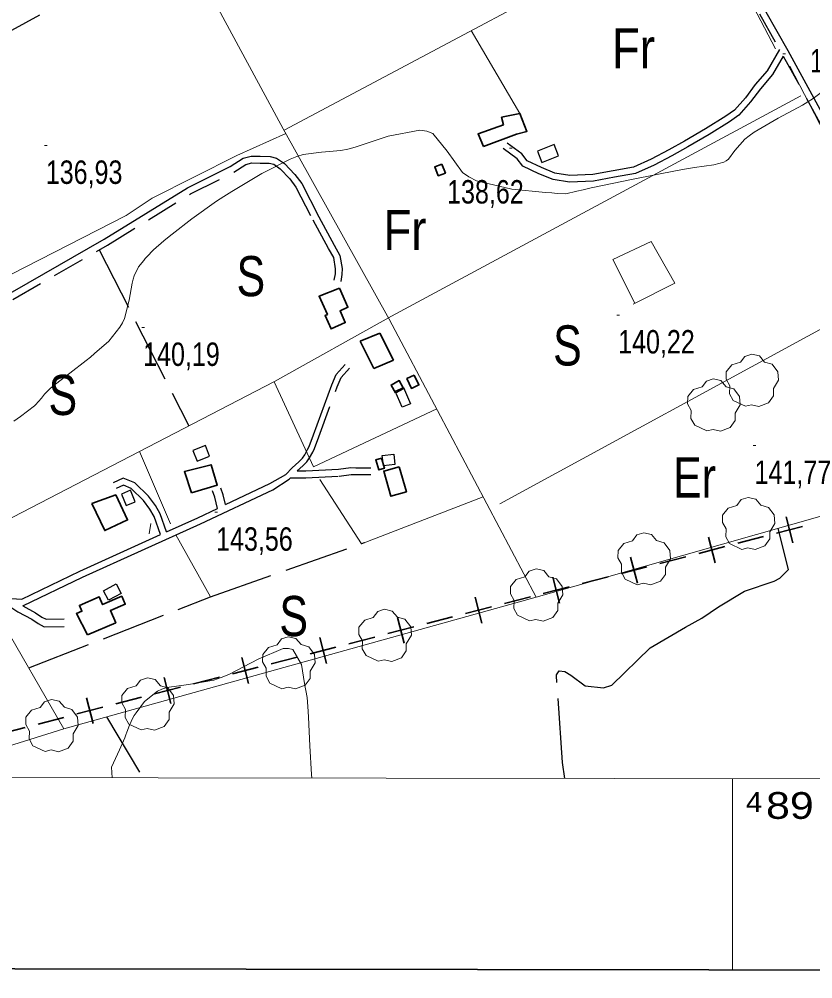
# Model space of a CAD drawing. Extents: x 487425 to 492029, y 4383576 to 4386788.
# Drawn here: x 488733.5 to 489030, y 4384052.3 to 4384410.8 of the extents above; entities that cross this region are included whole.
import ezdxf
from ezdxf.enums import TextEntityAlignment as Align

# ---------------------------------------------------------------- set-up
doc = ezdxf.new("R2010")
doc.units = 0
doc.header["$LTSCALE"] = 4
for name, pattern in [('DOTTED', [1.5, 0.3, -1.2]), ('LONG_DASHED', [7.5, 6, -1.5]), ('MEDIUM_DASHED', [4.5, 3, -1.5])]:
    doc.linetypes.add(name, pattern=pattern)
for name, color, linetype, lineweight in [('1', 7, 'Continuous', 13), ('2', 7, 'DOTTED', 13), ('21', 7, 'Continuous', 25), ('25', 7, 'LONG_DASHED', 25), ('29', 7, 'Continuous', 13), ('34', 7, 'Continuous', 35), ('38', 7, 'Continuous', 25), ('47', 7, 'Continuous', 35), ('49', 7, 'LONG_DASHED', 35), ('51', 7, 'Continuous', 13), ('7', 7, 'Continuous', 13), ('9', 7, 'Continuous', 13)]:
    doc.layers.add(name, color=color, linetype=linetype, lineweight=lineweight)
doc.layers.add('31', color=7, linetype='Continuous')

msp = doc.modelspace()

# ---------------------------------------------------------------- linework, layer by layer
at = {"layer": '1'}
msp.add_line((489000, 4384127.08), (489000, 4384055.68), dxfattribs=at)
at = {"layer": '1', "lineweight": 35}
msp.add_lwpolyline([(487611.46, 4386512.7), (491328.86, 4386507.3), (491325.3, 4384052.3), (487607.9, 4384057.7)], close=True, dxfattribs=at)
at = {"layer": '1'}
msp.add_lwpolyline([(487681.9, 4386441.2), (491258.2, 4386436), (491255.4, 4384123.8), (487678, 4384129)], close=True, dxfattribs=at)
at = {"layer": '21'}
for points in [[(488933.3, 4384363.95), (488927.11, 4384361.48), (488928.8, 4384357.25), (488934.99, 4384359.72)], [(488876.52, 4384265.79), (488873.97, 4384271.81), (488877.12, 4384273.14), (488879.67, 4384267.12)], [(488799.91, 4384245.66), (488804.62, 4384247.52), (488803.06, 4384251.55), (488798.35, 4384249.69)], [(488873.87, 4384244.44), (488869.54, 4384243.96), (488869.11, 4384247.79), (488873.44, 4384248.27)], [(488771.72, 4384233.37), (488773.47, 4384229.12), (488776.86, 4384230.54), (488775.11, 4384234.79)], [(488771.59, 4384196.24), (488766.8, 4384193.73), (488764.93, 4384197.29), (488769.72, 4384199.8)]]:
    msp.add_lwpolyline(points, close=True, dxfattribs=at)
at = {"layer": '25'}
for p, q in [((488793.82, 4384440.84), (488637.72, 4384356.35)), ((488763.36, 4384324.59), (488796.82, 4384258.88)), ((488766.06, 4384150.12), (488779.66, 4384127.4))]:
    msp.add_line(p, q, dxfattribs=at)
for points in [[(488937.38, 4384127.17), (488936.52, 4384133.07), (488934.19, 4384165.58), (488934.2, 4384165.81), (488935.26, 4384167.37), (488937.29, 4384167.05), (488939.6, 4384165.74), (488944.88, 4384161.78), (488951.77, 4384161.03), (488954.93, 4384161.97), (488969.2, 4384175.91), (488982.49, 4384183.64), (488988.53, 4384187.02), (488994.8, 4384191.3), (489004.47, 4384197.12), (489015.54, 4384200.82), (489017.66, 4384201.92), (489020.92, 4384205.26), (489017.03, 4384220.58)], [(488737.04, 4384168.42), (488804.89, 4384194.96), (488862.52, 4384215.24)]]:
    msp.add_lwpolyline(points, dxfattribs=at)
at = {"layer": '29'}
for points in [[(489004.79, 4384266.22), (489000.25, 4384268.34), (488998.84, 4384270.88), (488998.94, 4384273.86), (488997.57, 4384276.27), (488997.61, 4384279.02), (488999.77, 4384281.62), (489002.96, 4384282.62), (489004.61, 4384284.81), (489007.18, 4384285.64), (489010.04, 4384284.99), (489011.99, 4384282.72), (489014.8, 4384281.9), (489016.93, 4384279.05), (489017.17, 4384275.92), (489015.29, 4384272.77), (489015.29, 4384270.09), (489013.47, 4384267.48), (489009.85, 4384266.14), (489007.08, 4384266.77)], [(488990.43, 4384257), (488985.89, 4384259.12), (488984.48, 4384261.66), (488984.58, 4384264.64), (488983.21, 4384267.05), (488983.25, 4384269.8), (488985.41, 4384272.4), (488988.6, 4384273.4), (488990.25, 4384275.59), (488992.82, 4384276.42), (488995.68, 4384275.77), (488997.63, 4384273.5), (489000.44, 4384272.68), (489002.57, 4384269.83), (489002.81, 4384266.7), (489000.93, 4384263.55), (489000.93, 4384260.87), (488999.11, 4384258.26), (488995.49, 4384256.92), (488992.72, 4384257.55)], [(489003.43, 4384212.74), (488998.89, 4384214.86), (488997.48, 4384217.4), (488997.58, 4384220.38), (488996.21, 4384222.79), (488996.25, 4384225.54), (488998.41, 4384228.14), (489001.6, 4384229.14), (489003.25, 4384231.33), (489005.82, 4384232.16), (489008.68, 4384231.51), (489010.63, 4384229.24), (489013.44, 4384228.42), (489015.57, 4384225.57), (489015.81, 4384222.44), (489013.93, 4384219.29), (489013.93, 4384216.61), (489012.11, 4384214), (489008.49, 4384212.66), (489005.72, 4384213.29)], [(488964.42, 4384199.53), (488959.88, 4384201.65), (488958.47, 4384204.19), (488958.57, 4384207.17), (488957.2, 4384209.58), (488957.24, 4384212.33), (488959.4, 4384214.93), (488962.59, 4384215.93), (488964.24, 4384218.12), (488966.81, 4384218.95), (488969.67, 4384218.3), (488971.62, 4384216.03), (488974.43, 4384215.21), (488976.56, 4384212.36), (488976.8, 4384209.23), (488974.92, 4384206.08), (488974.92, 4384203.4), (488973.1, 4384200.79), (488969.48, 4384199.45), (488966.71, 4384200.08)], [(488924.2, 4384186.03), (488919.66, 4384188.15), (488918.25, 4384190.69), (488918.35, 4384193.67), (488916.98, 4384196.08), (488917.02, 4384198.83), (488919.18, 4384201.43), (488922.37, 4384202.43), (488924.02, 4384204.62), (488926.59, 4384205.45), (488929.45, 4384204.8), (488931.4, 4384202.53), (488934.21, 4384201.71), (488936.34, 4384198.86), (488936.58, 4384195.73), (488934.7, 4384192.58), (488934.7, 4384189.9), (488932.88, 4384187.29), (488929.26, 4384185.95), (488926.49, 4384186.58)], [(488867.61, 4384170.92), (488863.07, 4384173.04), (488861.66, 4384175.58), (488861.76, 4384178.56), (488860.39, 4384180.97), (488860.43, 4384183.72), (488862.59, 4384186.32), (488865.78, 4384187.32), (488867.43, 4384189.51), (488870, 4384190.34), (488872.86, 4384189.69), (488874.81, 4384187.42), (488877.62, 4384186.6), (488879.75, 4384183.75), (488879.99, 4384180.62), (488878.11, 4384177.47), (488878.11, 4384174.79), (488876.29, 4384172.18), (488872.67, 4384170.84), (488869.9, 4384171.47)], [(488831.64, 4384160.68), (488827.1, 4384162.8), (488825.69, 4384165.34), (488825.79, 4384168.32), (488824.42, 4384170.73), (488824.46, 4384173.48), (488826.62, 4384176.08), (488829.81, 4384177.08), (488831.46, 4384179.27), (488834.03, 4384180.1), (488836.89, 4384179.45), (488838.84, 4384177.18), (488841.65, 4384176.36), (488843.78, 4384173.51), (488844.02, 4384170.38), (488842.14, 4384167.23), (488842.14, 4384164.55), (488840.32, 4384161.94), (488836.7, 4384160.6), (488833.93, 4384161.23)], [(488779.02, 4384145.3), (488774.48, 4384147.42), (488773.07, 4384149.96), (488773.17, 4384152.94), (488771.8, 4384155.35), (488771.84, 4384158.1), (488774, 4384160.7), (488777.19, 4384161.7), (488778.84, 4384163.89), (488781.41, 4384164.72), (488784.27, 4384164.07), (488786.22, 4384161.8), (488789.03, 4384160.98), (488791.16, 4384158.13), (488791.4, 4384155), (488789.52, 4384151.85), (488789.52, 4384149.17), (488787.7, 4384146.56), (488784.08, 4384145.22), (488781.31, 4384145.85)], [(488743.14, 4384137.23), (488738.6, 4384139.35), (488737.19, 4384141.89), (488737.29, 4384144.87), (488735.92, 4384147.28), (488735.96, 4384150.03), (488738.12, 4384152.63), (488741.31, 4384153.63), (488742.96, 4384155.82), (488745.53, 4384156.65), (488748.39, 4384156), (488750.34, 4384153.73), (488753.15, 4384152.91), (488755.28, 4384150.06), (488755.52, 4384146.93), (488753.64, 4384143.78), (488753.64, 4384141.1), (488751.82, 4384138.49), (488748.2, 4384137.15), (488745.43, 4384137.78)]]:
    msp.add_lwpolyline(points, close=True, dxfattribs=at)
at = {"layer": '34'}
for p, q in [((489020.04, 4384224.84), (489022.54, 4384215.15)), ((489026.13, 4384221.25), (489016.44, 4384218.75)), ((488990.99, 4384217.34), (488993.49, 4384207.65)), ((489011.6, 4384217.5), (489001.92, 4384215)), ((488997.08, 4384213.74), (488987.4, 4384211.24)), ((488961.94, 4384209.83), (488964.44, 4384200.15)), ((488982.56, 4384209.99), (488972.87, 4384207.49)), ((488968.03, 4384206.24), (488958.35, 4384203.74)), ((488932.89, 4384202.33), (488935.39, 4384192.65)), ((488953.51, 4384202.49), (488943.83, 4384199.99)), ((488938.99, 4384198.74), (488929.3, 4384196.24)), ((488903.85, 4384194.83), (488906.35, 4384185.15)), ((488924.46, 4384194.99), (488914.78, 4384192.49)), ((488909.94, 4384191.24), (488900.26, 4384188.74)), ((488874.8, 4384187.33), (488877.3, 4384177.65)), ((488895.41, 4384187.49), (488885.73, 4384184.99)), ((488880.89, 4384183.74), (488871.21, 4384181.24)), ((488845.75, 4384179.83), (488848.25, 4384170.15)), ((488866.37, 4384179.99), (488856.69, 4384177.49)), ((488851.84, 4384176.24), (488842.16, 4384173.74)), ((488816.71, 4384172.33), (488819.21, 4384162.64)), ((488837.32, 4384172.49), (488827.64, 4384169.99)), ((488822.8, 4384168.74), (488813.12, 4384166.24)), ((488787.66, 4384164.83), (488790.16, 4384155.14)), ((488808.27, 4384164.99), (488798.59, 4384162.48)), ((488793.75, 4384161.23), (488784.07, 4384158.73)), ((488758.61, 4384157.32), (488761.11, 4384147.64)), ((488779.23, 4384157.48), (488769.54, 4384154.98)), ((488764.7, 4384153.73), (488755.02, 4384151.23)), ((488750.18, 4384149.98), (488740.5, 4384147.48)), ((488735.66, 4384146.23), (488725.97, 4384143.73))]:
    msp.add_line(p, q, dxfattribs=at)
at = {"layer": '38', "linetype": 'MEDIUM_DASHED'}
msp.add_line((489001.2, 4384428.51), (489017.54, 4384399.52), dxfattribs=at)
at = {"layer": '38'}
msp.add_line((488810.57, 4384229.47), (488827.11, 4384237.29), dxfattribs=at)
for points in [[(489004.23, 4384428.1), (489020.61, 4384399.05), (489040.89, 4384362.06), (489060.16, 4384327.09), (489065, 4384317.5)], [(489017.54, 4384399.52), (489012.9, 4384391.53), (489008.44, 4384386.38), (489004.8, 4384381.47), (489000.73, 4384376.85), (488997.44, 4384374.57), (488989.92, 4384369.87), (488982.08, 4384365.24), (488976.14, 4384361.95), (488969.61, 4384358.44), (488963.05, 4384355.51), (488955.43, 4384354.19), (488947.75, 4384352.72), (488939.22, 4384352.45), (488933.66, 4384353.31), (488928.64, 4384355.34), (488923.24, 4384357.83), (488921.3, 4384360.47), (488915.81, 4384364.45)], [(488686.73, 4384284.53), (488714.2, 4384299.4), (488765.22, 4384328.58), (488796.3, 4384347.83), (488812.36, 4384355.82), (488817.16, 4384358.91), (488820.12, 4384359.63), (488823.57, 4384359.6), (488827.23, 4384359.48), (488829.65, 4384358.93), (488832.6, 4384356.83), (488836.52, 4384352.83), (488839.05, 4384349.44), (488845.41, 4384336.99), (488851.2, 4384326.36), (488853.28, 4384322.56), (488854.11, 4384317.67), (488854, 4384315.45), (488853.59, 4384312.85)], [(488827.11, 4384237.29), (488833.07, 4384240.7), (488835.52, 4384243.23), (488837.97, 4384245.47), (488839.29, 4384246.77), (488840.15, 4384247.99), (488841.24, 4384250.04), (488841.81, 4384251.22), (488843.41, 4384255.57), (488850.31, 4384274.2), (488851.96, 4384278.11), (488855.24, 4384281.85)], [(488837.39, 4384242.06), (488840.58, 4384242.02), (488852.82, 4384242.71), (488857.36, 4384243.26), (488859.22, 4384243.24), (488864.84, 4384243.25)], [(488788.51, 4384219.28), (488786.13, 4384225.99), (488784.39, 4384229.1), (488781.74, 4384232.59), (488776.64, 4384237.57), (488772.37, 4384239.36), (488768.63, 4384237.62)], [(488734.87, 4384191.6), (488757.13, 4384202.37), (488801.23, 4384222.28), (488828.18, 4384235.03)], [(488810.57, 4384229.47), (488809.72, 4384233.14), (488808.82, 4384235.65)], [(488788.51, 4384219.28), (488800.18, 4384224.55), (488807.56, 4384228.04)], [(488714.57, 4384211.25), (488715.56, 4384211.12), (488718.15, 4384209.63), (488721.24, 4384207.17), (488722.38, 4384205.69), (488724.65, 4384200.32), (488726.1, 4384197.63), (488728.13, 4384195.25), (488729.55, 4384194.38), (488732.42, 4384194.2), (488734.46, 4384194.18), (488756.07, 4384204.64), (488786.29, 4384218.28)], [(488734.87, 4384191.6), (488739.61, 4384189.02), (488741.98, 4384187.42), (488743.52, 4384186.6), (488750.28, 4384186.73)]]:
    msp.add_lwpolyline(points, dxfattribs=at)
at = {"layer": '38', "linetype": 'MEDIUM_DASHED'}
for points in [[(489018.96, 4384396.99), (489014.94, 4384390.07), (489010.4, 4384384.81), (489006.75, 4384379.89), (489002.4, 4384374.96), (488998.82, 4384372.48), (488991.22, 4384367.73), (488983.33, 4384363.07), (488977.34, 4384359.76), (488970.72, 4384356.2), (488963.79, 4384353.1), (488955.88, 4384351.73), (488948.02, 4384350.22), (488939.07, 4384349.94), (488932.99, 4384350.88), (488927.65, 4384353.04), (488921.6, 4384355.83), (488919.51, 4384358.67), (488914.34, 4384362.43)], [(489018.96, 4384396.99), (489038.76, 4384360.88), (489058, 4384325.95), (489062.82, 4384316.4)], [(488691.88, 4384284.44), (488715.43, 4384297.18), (488766.52, 4384326.4), (488797.53, 4384345.61), (488813.62, 4384353.61), (488818.17, 4384356.55), (488820.41, 4384357.09), (488823.52, 4384357.06), (488826.9, 4384356.95), (488828.59, 4384356.57), (488830.95, 4384354.89), (488834.59, 4384351.18), (488836.89, 4384348.09), (488843.16, 4384335.8), (488848.97, 4384325.15), (488850.85, 4384321.72), (488851.56, 4384317.52), (488851.47, 4384315.71), (488851.08, 4384313.25)], [(488837.39, 4384242.06), (488839.43, 4384243.93), (488840.92, 4384245.39), (488841.96, 4384246.88), (488843.14, 4384249.08), (488843.76, 4384250.39), (488845.4, 4384254.83), (488852.29, 4384273.42), (488853.78, 4384276.97), (488856.84, 4384280.45)], [(488834.86, 4384239.49), (488840.63, 4384239.42), (488853.05, 4384240.12), (488857.51, 4384240.66), (488859.21, 4384240.64), (488864.84, 4384240.65)], [(488786.29, 4384218.28), (488783.9, 4384224.98), (488782.34, 4384227.76), (488779.9, 4384230.97), (488775.27, 4384235.5), (488772.42, 4384236.69), (488769.65, 4384235.41)], [(488828.18, 4384235.03), (488834.37, 4384238.98), (488834.86, 4384239.49)], [(488807.56, 4384228.04), (488806.6, 4384232.22), (488805.76, 4384234.54)], [(488729.24, 4384191.9), (488732.92, 4384189.43), (488738.14, 4384186.6), (488740.52, 4384184.99), (488742.85, 4384183.76), (488750.33, 4384183.9)]]:
    msp.add_lwpolyline(points, dxfattribs=at)
at = {"layer": '47'}
for points in [[(488906.96, 4384363.2), (488919.24, 4384367.86), (488923.15, 4384368.87), (488920.53, 4384375.57), (488913.68, 4384374.15), (488914.4, 4384371.29), (488904.91, 4384368.02)], [(488891.43, 4384356.62), (488892.71, 4384353.33), (488890.03, 4384352.29), (488888.75, 4384355.58)], [(488853.09, 4384310.25), (488856.31, 4384303.16), (488853.36, 4384301.83), (488855.32, 4384297.47), (488850.03, 4384295.09), (488847.77, 4384300.1), (488848.65, 4384300.5), (488845.55, 4384307.29)], [(488874.03, 4384271.15), (488877.12, 4384272.85), (488875.5, 4384275.78), (488872.41, 4384274.08)], [(488881.08, 4384277.82), (488882.8, 4384274.19), (488880.05, 4384272.88), (488878.33, 4384276.51)], [(488868.8, 4384246.82), (488869.94, 4384243.04), (488867.85, 4384242.41), (488866.71, 4384246.19)], [(488797.83, 4384233.83), (488807.47, 4384236.72), (488805.18, 4384244.33), (488795.22, 4384241.81)], [(488875.44, 4384243.6), (488878.13, 4384234.25), (488872.39, 4384232.6), (488869.7, 4384241.95)], [(488760.65, 4384229.9), (488765.41, 4384219.72), (488773.94, 4384223.72), (488769.55, 4384233.06)], [(488759.04, 4384180.85), (488769.52, 4384185.31), (488767.57, 4384189.86), (488773.09, 4384192.24), (488771.81, 4384195.2), (488764.65, 4384192.12), (488763.4, 4384194.99), (488755.98, 4384191.77), (488756.92, 4384189.59), (488754.85, 4384188.71)]]:
    msp.add_lwpolyline(points, close=True, dxfattribs=at)
at = {"layer": '49'}
msp.add_lwpolyline([(488868.2, 4384293.49), (488873.27, 4384283.46), (488866.03, 4384280.24), (488860.89, 4384290.5)], close=True, dxfattribs=at)
at = {"layer": '51'}
for p, q in [((488902.39, 4384406.56), (488920.53, 4384375.57)), ((489021.41, 4384393.26), (489058.26, 4384321.79)), ((488913.02, 4384229.74), (489059.77, 4384309.69)), ((488789.97, 4384222.29), (488778.39, 4384249.35)), ((488781.98, 4384218.48), (488782.62, 4384222.45)), ((488792.02, 4384218.14), (488804.89, 4384194.96)), ((488713.52, 4384209.13), (488750.16, 4384145.69))]:
    msp.add_line(p, q, dxfattribs=at)
for points in [[(488717.1, 4384583.17), (488755.31, 4384512.12), (488832.16, 4384369.83), (488871.71, 4384298.71), (488889.78, 4384264.59), (488926.57, 4384194.85), (489104.88, 4384245.56), (489187.75, 4384269.3), (489289.22, 4384299.81), (489411.33, 4384336.6), (489504.4, 4384367.43)], [(488832.46, 4384369.31), (488988.55, 4384452.45), (489016.08, 4384399.77)], [(488679.37, 4384279.66), (488714.13, 4384216.1), (488828.91, 4384275.49), (488872.55, 4384299.9), (489025.56, 4384382.1)], [(488682.04, 4384290.74), (488773.43, 4384337.41), (488783.18, 4384343.98), (488814.79, 4384359.82), (488833.14, 4384368.07)], [(488963.54, 4384304.7), (488955.24, 4384321.01), (488969.65, 4384327.75)], [(488969.65, 4384327.75), (488978.47, 4384312.19), (488962.85, 4384304.35)], [(488828.68, 4384275.37), (488843.4, 4384243.51), (488889.46, 4384265.2)], [(488845.75, 4384238.83), (488861.38, 4384214.8), (488906.82, 4384232.3)], [(488697.57, 4384129.19), (488750.16, 4384145.69), (488926.57, 4384194.85)]]:
    msp.add_lwpolyline(points, dxfattribs=at)
at = {"layer": '7'}
for p, q in [((489018.78, 4384397.86), (489019.78, 4384397.86)), ((488742.91, 4384363.63), (488743.91, 4384363.63)), ((488916.65, 4384362.63), (488917.65, 4384362.63)), ((488956.76, 4384300.28), (488957.76, 4384300.28)), ((488779.28, 4384295.63), (488780.28, 4384295.63)), ((489007.74, 4384251.54), (489008.74, 4384251.54)), ((488806.55, 4384226.59), (488807.55, 4384226.59))]:
    msp.add_line(p, q, dxfattribs=at)
at = {"layer": '9'}
msp.add_line((488768.24, 4384127.42), (488767.97, 4384131.33), dxfattribs=at)
for points in [[(488731.49, 4384260.61), (488734, 4384262.38), (488739.15, 4384266.37), (488741, 4384268.3), (488741.44, 4384268.78), (488741.83, 4384269.24), (488742.97, 4384270.74), (488744.97, 4384272.76), (488745.9, 4384273.56), (488747, 4384274.45), (488752.36, 4384278.55), (488758.51, 4384283.29), (488760.11, 4384284.59), (488761.67, 4384285.89), (488766.93, 4384290.54), (488771.13, 4384295.7), (488772.01, 4384297.31), (488772.78, 4384299.01), (488774.56, 4384305.84), (488775.7, 4384312.23), (488776.07, 4384313.66), (488776.47, 4384314.93), (488778.08, 4384318.28), (488780.01, 4384320.69), (488780.6, 4384321.37), (488781.22, 4384322.06), (488783.68, 4384324.59), (488787.48, 4384327.94), (488788.94, 4384329.14), (488790.58, 4384330.46), (488797.99, 4384336.21), (488807.21, 4384342.78), (488809.99, 4384344.61), (488812.87, 4384346.45), (488824.1, 4384353.15), (488834.75, 4384358.48), (488837.26, 4384359.45), (488839.59, 4384360.21), (488846.41, 4384361.13), (488853.63, 4384361.73), (488856.21, 4384362.29), (488859.04, 4384363.01), (488871.34, 4384367.05), (488883.2, 4384369.32), (488885.75, 4384368.93), (488887.98, 4384368.11), (488893.38, 4384361.46), (488899.1, 4384353.51), (488901.53, 4384351.85), (488904.33, 4384350.44), (488917.5, 4384347.32), (488930.07, 4384346.1), (488932.49, 4384345.89), (488934.46, 4384345.73), (488937.74, 4384345.61), (488941.77, 4384346.57), (488944.21, 4384347.1), (488947.22, 4384347.73), (488962.86, 4384350.97), (488979.26, 4384354.21), (488982.75, 4384354.85), (488985.79, 4384355.38), (488992.96, 4384356.37), (488996.74, 4384357.35), (488997.63, 4384357.87), (488998.46, 4384358.5), (489000.92, 4384361.71), (489004.63, 4384365.95), (489006.26, 4384367.24), (489008.14, 4384368.57), (489017.07, 4384373.78), (489026.12, 4384378.72), (489028.08, 4384379.87), (489029.79, 4384380.94), (489033.97, 4384384.03)], [(488767.97, 4384131.33), (488770.93, 4384137.84), (488772.91, 4384142.37), (488773.34, 4384143.42), (488773.72, 4384144.38), (488774.67, 4384147.11), (488775.91, 4384149.77), (488776.48, 4384150.68), (488777.13, 4384151.67), (488780.31, 4384155.9), (488785.13, 4384159.75), (488786.82, 4384160.51), (488788.68, 4384161.14), (488796.69, 4384162.29), (488806.19, 4384163.9), (488808.98, 4384164.82), (488811.84, 4384165.94), (488822.76, 4384171.68), (488832.16, 4384175.69), (488834.07, 4384175.72), (488835.67, 4384175.28), (488838.95, 4384169.77), (488840.06, 4384162.65), (488840.3, 4384161.2), (488840.51, 4384159.98), (488841.02, 4384157.42), (488841.37, 4384153.99), (488841.49, 4384152.21), (488841.61, 4384150.08), (488842.12, 4384139.38), (488842.73, 4384128.65), (488842.85, 4384127.31)]]:
    msp.add_lwpolyline(points, dxfattribs=at)

# ---------------------------------------------------------------- texts
at = {"layer": '2'}
for s, height, width, p in [('4', 7.5, 1.1, (489004.99, 4384114.57)), ('89  ', 10, 1.2, (489012.49, 4384112.06))]:
    msp.add_text(s, height=height, rotation=359.917, dxfattribs=dict(at, width=width)).set_placement(p)
at = {"layer": '31'}
for s, width, p in [('Fr', 0.85, (488962.96, 4384392.37)), ('Fr', 0.85, (488877.62, 4384324.56)), ('S', 0.8, (488820.03, 4384307.3)), ('S', 0.8, (488938.32, 4384281.41)), ('S', 0.8, (488749.78, 4384262.92)), ('Er', 0.8, (488985.78, 4384232.1)), ('S', 0.8, (488836.04, 4384180.32))]:
    msp.add_text(s, height=15, dxfattribs=dict(at, width=width)).set_placement(p, align=Align.CENTER)
at = {"layer": '7'}
for s, width, p in [('138,21', 0.75, (489028.99, 4384390.89)), ('136,93', 0.8, (488743.41, 4384349.26)), ('138,62', 0.8, (488893.36, 4384341.93)), ('140,22', 0.8, (488957.26, 4384285.91)), ('140,19', 0.8, (488779.78, 4384281.26)), ('141,77', 0.8, (489008.24, 4384237.17)), ('143,56', 0.8, (488807.05, 4384212.22))]:
    msp.add_text(s, height=8.75, dxfattribs=dict(at, width=width)).set_placement(p)

doc.saveas('drawing.dxf')
